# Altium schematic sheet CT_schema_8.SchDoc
size 274 x 160 mm
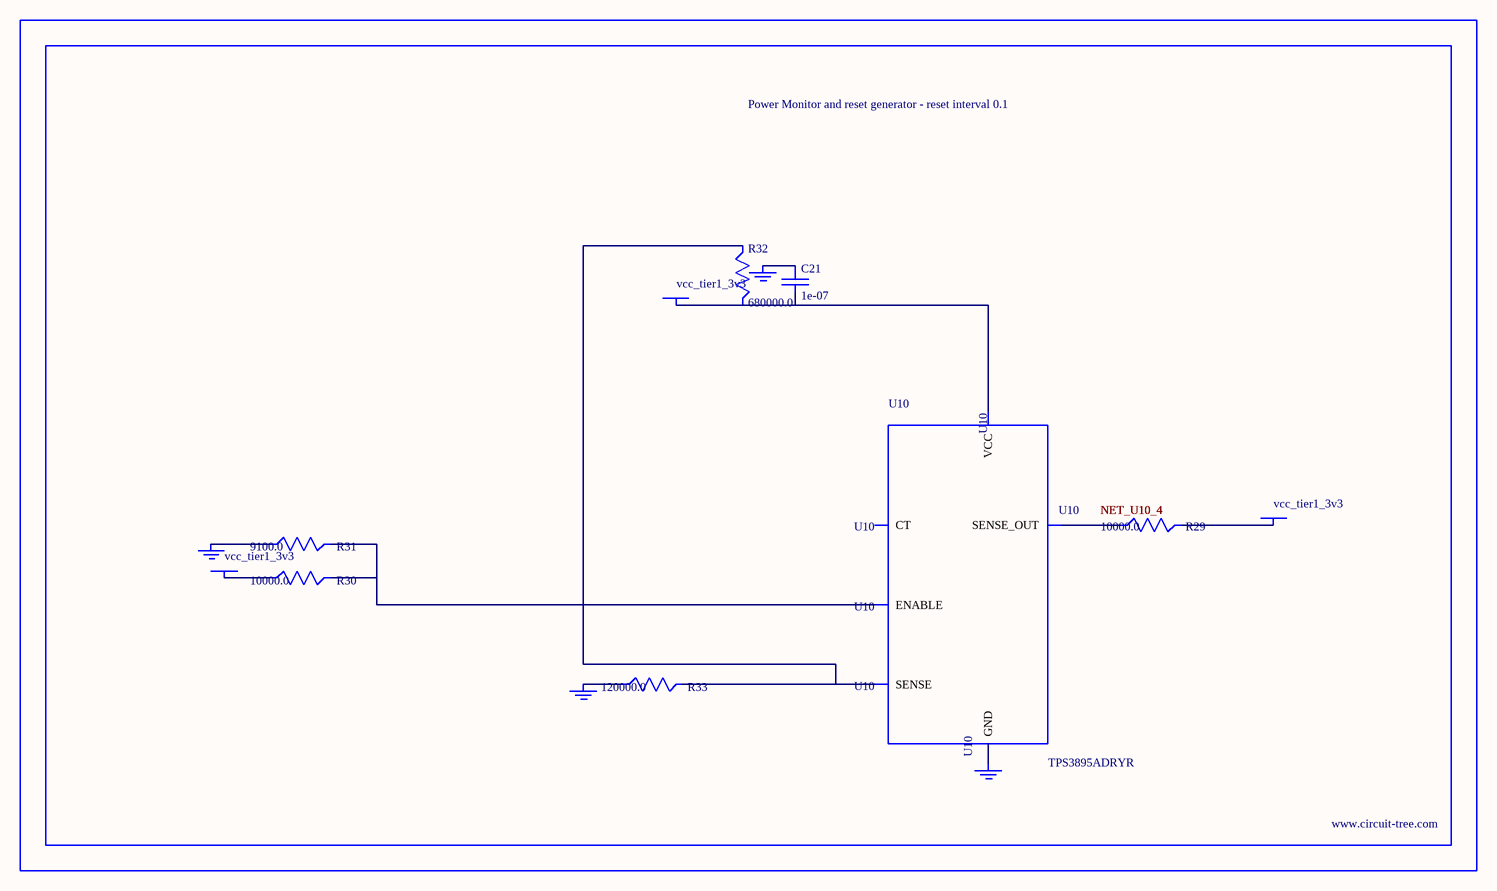
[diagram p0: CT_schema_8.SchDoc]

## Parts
BORDER7  (no value)
C21  1e-07  [C0402]
GND_INSTANCE_7_0  (no value)
GND_INSTANCE_7_1  (no value)
GND_INSTANCE_7_2  (no value)
GND_INSTANCE_7_3  (no value)
POWER_INSTANCE_7_0  vcc_tier1_3v3
POWER_INSTANCE_7_1  vcc_tier1_3v3
POWER_INSTANCE_7_2  vcc_tier1_3v3
R29  10000.0  [R0603]
R30  10000.0  [R0603]
R31  9100.0  [R0603]
R32  680000.0  [R0603]
R33  120000.0  [R0603]
U10  TPS3895ADRYR  [SON-6]

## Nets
NetC21_1: C21.1 GND_INSTANCE_7_2.0(GND)
NetC21_2: C21.2 POWER_INSTANCE_7_2.0(PWR) R32.2 U10.6(VCC)
NetGND_INSTANCE_7_0_0: GND_INSTANCE_7_0.0(GND) R31.1
NetGND_INSTANCE_7_1_0: GND_INSTANCE_7_1.0(GND) R33.1
NetGND_INSTANCE_7_3_0: GND_INSTANCE_7_3.0(GND) U10.2(GND)
NetPOWER_INSTANCE_7_0_0: POWER_INSTANCE_7_0.0(PWR) R30.1
NetPOWER_INSTANCE_7_1_0: POWER_INSTANCE_7_1.0(PWR) R29.2
NetR29_1: R29.1 U10.4(SENSE_OUT)
NetR30_2: R30.2 R31.2 U10.1(ENABLE)
NetR32_1: R32.1 R33.2 U10.3(SENSE)

Not connected (* = marked no-connect by the designer): U10 5(CT)

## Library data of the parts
BORDER7 = BORDER_PAGE7
C21 = C0402C104K3RACTU
GND_INSTANCE_7_0-GND_INSTANCE_7_3 = GND
POWER_INSTANCE_7_0-POWER_INSTANCE_7_2 = PWR
R29 R30 = RC0603JR-0710KL
R31 = RC0603JR-079K1L
R32 = RC0603JR-07680KL
R33 = RC0603JR-07120KL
